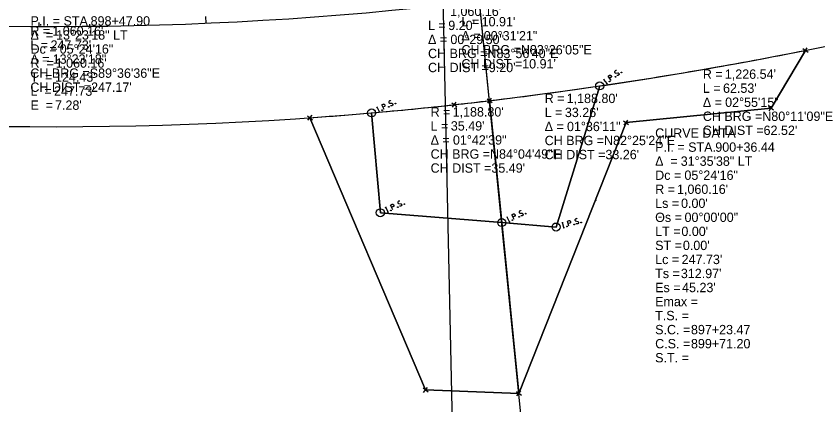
# Model space of a CAD drawing. Extents: x 2379325 to 2382869, y 256594 to 258871.
# Drawn here: x 2382072.5 to 2382312.6, y 257773.3 to 257889.6 of the extents above; entities that cross this region are included whole.
import ezdxf

# ---------------------------------------------------------------- set-up
doc = ezdxf.new("R2010")
doc.units = 0
for name, color, linetype in [('Default', 7, 'Continuous'), ('DR_P_Culvert3D', 7, 'Continuous'), ('DR_P_Dike', 7, 'Continuous'), ('DR_P_Ditch', 7, 'Continuous'), ('DR_P_Drainage_Area', 7, 'Continuous'), ('DR_P_Headwall', 7, 'Continuous'), ('DR_P_Storm_Sewer', 7, 'Continuous'), ('DR_X_Culvert', 7, 'Continuous'), ('DR_X_Culvert3D', 7, 'Continuous'), ('DR_X_Storm_Sewer', 7, 'Continuous'), ('PF_X_Ground_Line', 7, 'Continuous'), ('SC_Scratch1', 7, 'Continuous'), ('SC_Scratch2', 7, 'Continuous'), ('SC_Scratch4', 7, 'Continuous')]:
    doc.layers.add(name, color=color, linetype=linetype)

msp = doc.modelspace()

# ---------------------------------------------------------------- linework, layer by layer
at = {"layer": 'DR_P_Culvert3D'}
for p, q in [((2382298.56, 257862.08), (2382308.87, 257879.36)), ((2382255.15, 257857.75), (2382298.56, 257862.08)), ((2382160.54, 257859.2), (2382195.13, 257777.78)), ((2382223.08, 257776.74), (2382255.15, 257857.75)), ((2382195.13, 257777.78), (2382223.08, 257776.74))]:
    msp.add_line(p, q, dxfattribs=at)
at = {"layer": 'DR_P_Dike'}
for p, q in [((2382247.26, 257868.7), (2382234.2, 257826.5)), ((2382214.29, 257864.32), (2382217.95, 257827.82)), ((2382217.95, 257827.82), (2382214.29, 257864.32)), ((2382181.6, 257830.77), (2382178.99, 257860.65)), ((2382217.95, 257827.82), (2382181.6, 257830.77)), ((2382234.2, 257826.5), (2382217.95, 257827.82))]:
    msp.add_line(p, q, dxfattribs=at)
for centre, radius, start, end in [((2382069.07, 259082.23), 1226.54, 276.79975, 278.35358), ((2382084.05, 258946.67), 1090.16, 274.99624, 276.30412), ((2382069.07, 259082.23), 1226.54, 276.30412, 276.79975)]:
    msp.add_arc(centre, radius, start, end, dxfattribs=at)
at = {"layer": 'DR_P_Ditch'}
for points in [[(2382252.25, 257873.34), (2382252.21, 257873.34), (2382252.17, 257873.34), (2382252.07, 257873.31), (2382251.96, 257873.26), (2382251.89, 257873.21), (2382251.86, 257873.19), (2382251.77, 257873.07), (2382251.72, 257872.94), (2382251.72, 257872.81), (2382251.76, 257872.72), (2382251.81, 257872.66), (2382251.89, 257872.59), (2382252.01, 257872.57), (2382252.72, 257872.64), (2382252.8, 257872.63), (2382252.84, 257872.6), (2382252.91, 257872.55), (2382252.95, 257872.49), (2382252.99, 257872.43), (2382253.01, 257872.38), (2382253.03, 257872.32), (2382253.04, 257872.26), (2382253.05, 257872.22), (2382253.05, 257872.17), (2382253.03, 257872.13), (2382253.01, 257872.08), (2382253, 257872.05), (2382252.92, 257871.98), (2382252.8, 257871.89), (2382252.71, 257871.85), (2382252.54, 257871.83), (2382252.42, 257871.84)], [(2382253.67, 257872.81), (2382253.71, 257872.85), (2382253.75, 257872.85), (2382253.81, 257872.83), (2382253.85, 257872.78), (2382253.85, 257872.72), (2382253.84, 257872.68), (2382253.79, 257872.64), (2382253.75, 257872.64), (2382253.7, 257872.66), (2382253.66, 257872.71), (2382253.65, 257872.77), (2382253.67, 257872.81)], [(2382248.39, 257870.56), (2382248.67, 257870.77)], [(2382249.5, 257869.39), (2382248.53, 257870.67)], [(2382250.74, 257870.33), (2382249.78, 257871.61), (2382250.2, 257871.93), (2382250.25, 257871.95), (2382250.33, 257871.98), (2382250.37, 257871.98), (2382250.41, 257871.98), (2382250.49, 257871.95), (2382250.55, 257871.92), (2382250.63, 257871.86), (2382250.72, 257871.74), (2382250.74, 257871.69), (2382250.77, 257871.62), (2382250.79, 257871.52), (2382250.78, 257871.46), (2382250.76, 257871.42), (2382250.74, 257871.37), (2382250.67, 257871.31), (2382250.25, 257870.99)], [(2382250.13, 257870.14), (2382250.18, 257870.17), (2382250.22, 257870.17), (2382250.27, 257870.15), (2382250.31, 257870.1), (2382250.32, 257870.04), (2382250.31, 257870), (2382250.26, 257869.97), (2382250.22, 257869.97), (2382250.16, 257869.99), (2382250.12, 257870.04), (2382250.12, 257870.1), (2382250.13, 257870.14)], [(2382251.93, 257871.5), (2382251.97, 257871.53), (2382252.01, 257871.53), (2382252.07, 257871.51), (2382252.11, 257871.46), (2382252.11, 257871.4), (2382252.1, 257871.36), (2382252.05, 257871.32), (2382252.01, 257871.32), (2382251.96, 257871.35), (2382251.92, 257871.4), (2382251.91, 257871.46), (2382251.93, 257871.5)], [(2382249.36, 257869.28), (2382249.64, 257869.5)], [(2382182.71, 257861.61), (2382182, 257863.05), (2382182.47, 257863.28), (2382182.53, 257863.3), (2382182.61, 257863.31), (2382182.65, 257863.3), (2382182.69, 257863.29), (2382182.76, 257863.26), (2382182.81, 257863.21), (2382182.88, 257863.13), (2382182.95, 257863), (2382182.96, 257862.95), (2382182.97, 257862.87), (2382182.97, 257862.77), (2382182.95, 257862.72), (2382182.93, 257862.68), (2382182.89, 257862.63), (2382182.82, 257862.58), (2382182.35, 257862.35)], [(2382184.74, 257864.29), (2382184.71, 257864.3), (2382184.67, 257864.31), (2382184.57, 257864.3), (2382184.45, 257864.26), (2382184.37, 257864.23), (2382184.34, 257864.21), (2382184.23, 257864.11), (2382184.15, 257863.99), (2382184.13, 257863.87), (2382184.15, 257863.77), (2382184.19, 257863.7), (2382184.25, 257863.62), (2382184.37, 257863.58), (2382185.08, 257863.51), (2382185.15, 257863.49), (2382185.19, 257863.45), (2382185.25, 257863.4), (2382185.28, 257863.33), (2382185.31, 257863.26), (2382185.32, 257863.21), (2382185.33, 257863.14), (2382185.33, 257863.08), (2382185.33, 257863.04), (2382185.31, 257862.99), (2382185.29, 257862.96), (2382185.27, 257862.91), (2382185.24, 257862.89), (2382185.16, 257862.83), (2382185.02, 257862.76), (2382184.92, 257862.74), (2382184.75, 257862.76), (2382184.64, 257862.79)], [(2382186.04, 257863.51), (2382186.09, 257863.53), (2382186.13, 257863.53), (2382186.18, 257863.5), (2382186.21, 257863.44), (2382186.2, 257863.38), (2382186.19, 257863.34), (2382186.14, 257863.32), (2382186.1, 257863.33), (2382186.04, 257863.36), (2382186.02, 257863.41), (2382186.02, 257863.47), (2382186.04, 257863.51)], [(2382180.44, 257862.27), (2382180.76, 257862.43)], [(2382181.31, 257860.92), (2382180.6, 257862.35)], [(2382181.15, 257860.84), (2382181.47, 257861)], [(2382182.07, 257861.54), (2382182.12, 257861.56), (2382182.16, 257861.55), (2382182.22, 257861.52), (2382182.24, 257861.47), (2382182.24, 257861.41), (2382182.22, 257861.37), (2382182.17, 257861.34), (2382182.13, 257861.35), (2382182.08, 257861.38), (2382182.05, 257861.44), (2382182.05, 257861.5), (2382182.07, 257861.54)], [(2382184.09, 257862.54), (2382184.14, 257862.56), (2382184.18, 257862.55), (2382184.23, 257862.52), (2382184.26, 257862.47), (2382184.25, 257862.41), (2382184.23, 257862.37), (2382184.18, 257862.35), (2382184.14, 257862.35), (2382184.09, 257862.38), (2382184.06, 257862.44), (2382184.07, 257862.5), (2382184.09, 257862.54)], [(2382187.45, 257834.25), (2382187.42, 257834.26), (2382187.38, 257834.27), (2382187.27, 257834.26), (2382187.15, 257834.24), (2382187.07, 257834.2), (2382187.04, 257834.18), (2382186.93, 257834.09), (2382186.85, 257833.97), (2382186.82, 257833.85), (2382186.84, 257833.75), (2382186.88, 257833.68), (2382186.94, 257833.59), (2382187.06, 257833.55), (2382187.76, 257833.47), (2382187.84, 257833.44), (2382187.88, 257833.41), (2382187.93, 257833.35), (2382187.96, 257833.28), (2382187.98, 257833.21), (2382187.99, 257833.16), (2382188, 257833.09), (2382188, 257833.03), (2382188, 257832.99), (2382187.98, 257832.94), (2382187.96, 257832.91), (2382187.94, 257832.86), (2382187.91, 257832.84), (2382187.83, 257832.79), (2382187.69, 257832.72), (2382187.59, 257832.7), (2382187.42, 257832.72), (2382187.31, 257832.75)], [(2382183.09, 257832.35), (2382183.41, 257832.5)], [(2382183.93, 257830.97), (2382183.25, 257832.42)], [(2382185.35, 257831.63), (2382184.67, 257833.08), (2382185.15, 257833.31), (2382185.21, 257833.32), (2382185.29, 257833.33), (2382185.33, 257833.32), (2382185.37, 257833.31), (2382185.44, 257833.27), (2382185.49, 257833.23), (2382185.56, 257833.15), (2382185.62, 257833.01), (2382185.63, 257832.96), (2382185.64, 257832.88), (2382185.64, 257832.78), (2382185.62, 257832.73), (2382185.6, 257832.69), (2382185.56, 257832.65), (2382185.48, 257832.6), (2382185, 257832.37)], [(2382186.75, 257832.52), (2382186.8, 257832.54), (2382186.84, 257832.53), (2382186.89, 257832.5), (2382186.91, 257832.44), (2382186.91, 257832.38), (2382186.89, 257832.35), (2382186.84, 257832.32), (2382186.8, 257832.33), (2382186.74, 257832.37), (2382186.72, 257832.42), (2382186.73, 257832.48), (2382186.75, 257832.52)], [(2382188.73, 257833.44), (2382188.77, 257833.46), (2382188.82, 257833.45), (2382188.87, 257833.42), (2382188.89, 257833.37), (2382188.88, 257833.31), (2382188.87, 257833.27), (2382188.82, 257833.25), (2382188.77, 257833.25), (2382188.72, 257833.29), (2382188.7, 257833.34), (2382188.71, 257833.4), (2382188.73, 257833.44)], [(2382183.77, 257830.9), (2382184.09, 257831.05)], [(2382184.71, 257831.57), (2382184.76, 257831.59), (2382184.8, 257831.58), (2382184.85, 257831.55), (2382184.88, 257831.5), (2382184.87, 257831.44), (2382184.85, 257831.4), (2382184.8, 257831.38), (2382184.76, 257831.38), (2382184.71, 257831.42), (2382184.68, 257831.47), (2382184.69, 257831.53), (2382184.71, 257831.57)], [(2382219.43, 257829.42), (2382219.74, 257829.57)], [(2382220.28, 257828.05), (2382219.58, 257829.49)], [(2382221.69, 257828.73), (2382220.99, 257830.17), (2382221.47, 257830.4), (2382221.53, 257830.41), (2382221.61, 257830.42), (2382221.65, 257830.42), (2382221.69, 257830.41), (2382221.76, 257830.37), (2382221.81, 257830.33), (2382221.88, 257830.25), (2382221.94, 257830.11), (2382221.95, 257830.06), (2382221.97, 257829.98), (2382221.96, 257829.88), (2382221.94, 257829.83), (2382221.92, 257829.79), (2382221.88, 257829.75), (2382221.81, 257829.7), (2382221.33, 257829.47)], [(2382223.08, 257829.64), (2382223.12, 257829.66), (2382223.17, 257829.65), (2382223.22, 257829.62), (2382223.24, 257829.56), (2382223.24, 257829.5), (2382223.22, 257829.47), (2382223.17, 257829.44), (2382223.13, 257829.45), (2382223.08, 257829.48), (2382223.05, 257829.54), (2382223.06, 257829.6), (2382223.08, 257829.64)], [(2382223.75, 257831.38), (2382223.72, 257831.39), (2382223.68, 257831.4), (2382223.58, 257831.39), (2382223.46, 257831.36), (2382223.38, 257831.32), (2382223.35, 257831.31), (2382223.24, 257831.21), (2382223.16, 257831.09), (2382223.13, 257830.96), (2382223.16, 257830.86), (2382223.19, 257830.8), (2382223.25, 257830.71), (2382223.37, 257830.67), (2382224.08, 257830.6), (2382224.15, 257830.57), (2382224.19, 257830.54), (2382224.25, 257830.48), (2382224.28, 257830.41), (2382224.3, 257830.34), (2382224.31, 257830.29), (2382224.32, 257830.22), (2382224.32, 257830.17), (2382224.32, 257830.12), (2382224.31, 257830.08), (2382224.29, 257830.04), (2382224.26, 257830), (2382224.24, 257829.97), (2382224.15, 257829.92), (2382224.01, 257829.85), (2382223.91, 257829.83), (2382223.74, 257829.85), (2382223.63, 257829.88)], [(2382225.04, 257830.58), (2382225.09, 257830.61), (2382225.13, 257830.6), (2382225.18, 257830.57), (2382225.21, 257830.51), (2382225.2, 257830.45), (2382225.18, 257830.41), (2382225.13, 257830.39), (2382225.09, 257830.4), (2382225.04, 257830.43), (2382225.02, 257830.49), (2382225.02, 257830.55), (2382225.04, 257830.58)], [(2382220.12, 257827.97), (2382220.44, 257828.13)], [(2382221.05, 257828.66), (2382221.1, 257828.68), (2382221.14, 257828.68), (2382221.19, 257828.64), (2382221.22, 257828.59), (2382221.21, 257828.53), (2382221.19, 257828.49), (2382221.14, 257828.47), (2382221.1, 257828.48), (2382221.05, 257828.51), (2382221.02, 257828.56), (2382221.03, 257828.62), (2382221.05, 257828.66)], [(2382235.94, 257827.81), (2382236.28, 257827.9)], [(2382236.53, 257826.31), (2382236.11, 257827.86)], [(2382238.04, 257826.73), (2382237.62, 257828.27), (2382238.13, 257828.41), (2382238.18, 257828.41), (2382238.26, 257828.41), (2382238.3, 257828.4), (2382238.34, 257828.38), (2382238.4, 257828.33), (2382238.45, 257828.28), (2382238.5, 257828.19), (2382238.54, 257828.04), (2382238.54, 257827.99), (2382238.54, 257827.91), (2382238.52, 257827.82), (2382238.49, 257827.77), (2382238.46, 257827.73), (2382238.42, 257827.7), (2382238.33, 257827.66), (2382237.82, 257827.52)], [(2382239.57, 257827.37), (2382239.62, 257827.39), (2382239.66, 257827.37), (2382239.71, 257827.33), (2382239.72, 257827.27), (2382239.7, 257827.21), (2382239.68, 257827.18), (2382239.63, 257827.17), (2382239.59, 257827.18), (2382239.54, 257827.22), (2382239.52, 257827.28), (2382239.54, 257827.34), (2382239.57, 257827.37)], [(2382240.55, 257828.96), (2382240.52, 257828.98), (2382240.48, 257829), (2382240.38, 257829.01), (2382240.25, 257829), (2382240.17, 257828.98), (2382240.14, 257828.97), (2382240.01, 257828.89), (2382239.91, 257828.79), (2382239.86, 257828.67), (2382239.87, 257828.57), (2382239.89, 257828.49), (2382239.94, 257828.4), (2382240.04, 257828.34), (2382240.73, 257828.14), (2382240.8, 257828.1), (2382240.83, 257828.06), (2382240.87, 257827.99), (2382240.89, 257827.92), (2382240.9, 257827.84), (2382240.9, 257827.79), (2382240.9, 257827.73), (2382240.89, 257827.67), (2382240.88, 257827.63), (2382240.86, 257827.58), (2382240.83, 257827.55), (2382240.8, 257827.52), (2382240.77, 257827.49), (2382240.68, 257827.46), (2382240.53, 257827.42), (2382240.43, 257827.41), (2382240.26, 257827.46), (2382240.16, 257827.51)], [(2382241.67, 257827.95), (2382241.73, 257827.97), (2382241.76, 257827.95), (2382241.81, 257827.91), (2382241.83, 257827.85), (2382241.81, 257827.79), (2382241.78, 257827.76), (2382241.73, 257827.75), (2382241.69, 257827.76), (2382241.65, 257827.8), (2382241.63, 257827.86), (2382241.65, 257827.92), (2382241.67, 257827.95)], [(2382236.36, 257826.27), (2382236.7, 257826.36)], [(2382237.4, 257826.77), (2382237.45, 257826.79), (2382237.49, 257826.77), (2382237.54, 257826.73), (2382237.55, 257826.67), (2382237.54, 257826.62), (2382237.51, 257826.58), (2382237.46, 257826.57), (2382237.42, 257826.58), (2382237.37, 257826.62), (2382237.36, 257826.68), (2382237.38, 257826.74), (2382237.4, 257826.77)]]:
    msp.add_lwpolyline(points, dxfattribs=at)
for centre in [(2382247.26, 257868.7), (2382178.99, 257860.65), (2382181.6, 257830.77), (2382217.95, 257827.82), (2382234.2, 257826.5)]:
    msp.add_circle(centre, 1.2, dxfattribs=at)
at = {"layer": 'DR_P_Drainage_Area'}
for p, q in [((2382308.87, 257879.36), (2382298.56, 257862.08)), ((2382308.87, 257879.36), (2382298.56, 257862.08)), ((2382234.2, 257826.5), (2382247.26, 257868.7)), ((2382178.99, 257860.65), (2382181.6, 257830.77)), ((2382298.56, 257862.08), (2382255.15, 257857.75)), ((2382298.56, 257862.08), (2382255.15, 257857.75)), ((2382195.13, 257777.78), (2382160.54, 257859.2)), ((2382255.15, 257857.75), (2382223.08, 257776.74)), ((2382255.15, 257857.75), (2382223.08, 257776.74)), ((2382181.6, 257830.77), (2382217.95, 257827.82)), ((2382217.95, 257827.82), (2382223.08, 257776.74)), ((2382223.08, 257776.74), (2382217.95, 257827.82)), ((2382217.95, 257827.82), (2382234.2, 257826.5)), ((2382223.08, 257776.74), (2382217.95, 257827.82)), ((2382217.95, 257827.82), (2382234.2, 257826.5)), ((2382223.08, 257776.74), (2382195.13, 257777.78))]:
    msp.add_line(p, q, dxfattribs=at)
for centre, radius, start, end in [((2382069.07, 259082.23), 1226.54, 278.35358, 281.27454), ((2382069.07, 259082.23), 1226.54, 278.35358, 281.27454), ((2382084.05, 258946.67), 1090.16, 274.02344, 274.99624)]:
    msp.add_arc(centre, radius, start, end, dxfattribs=at)
at = {"layer": 'DR_P_Headwall'}
for centre, radius, start, end in [((2382069.07, 259082.23), 1226.54, 276.30412, 294.43398), ((2382084.05, 258946.67), 1090.16, 262.91573, 276.30412)]:
    msp.add_arc(centre, radius, start, end, dxfattribs=at)
at = {"layer": 'DR_P_Storm_Sewer'}
for p, q in [((2382308.08, 257879.87), (2382309.66, 257878.84)), ((2382308.36, 257878.57), (2382309.39, 257880.15)), ((2382203.01, 257863.69), (2382204.49, 257862.52)), ((2382203.17, 257862.36), (2382204.33, 257863.85)), ((2382213.54, 257864.88), (2382215.05, 257863.75)), ((2382213.73, 257863.56), (2382214.86, 257865.07)), ((2382297.78, 257862.61), (2382299.34, 257861.55)), ((2382298.03, 257861.3), (2382299.09, 257862.86)), ((2382159.82, 257859.81), (2382161.26, 257858.59)), ((2382159.93, 257858.48), (2382161.15, 257859.92)), ((2382254.39, 257858.3), (2382255.91, 257857.19)), ((2382254.6, 257856.98), (2382255.7, 257858.51)), ((2382194.39, 257778.36), (2382195.87, 257777.19)), ((2382194.54, 257777.04), (2382195.71, 257778.52)), ((2382222.33, 257777.31), (2382223.83, 257776.17)), ((2382222.5, 257775.99), (2382223.65, 257777.49))]:
    msp.add_line(p, q, dxfattribs=at)
at = {"layer": 'DR_X_Culvert3D'}
for p, q in [((2382129.48, 257887.49), (2382129.39, 257889.48)), ((2382079.49, 257886.52), (2382079.5, 257887.72))]:
    msp.add_line(p, q, dxfattribs=at)
at = {"layer": 'DR_X_Storm_Sewer'}
for q in [(2382211.21, 257895.08), (2382211.23, 257894.88)]:
    msp.add_line((2382240.29, 257605.16), q, dxfattribs=at)
at = {"layer": 'PF_X_Ground_Line'}
msp.add_line((2382227.19, 256666.69), (2382192.17, 258272.85), dxfattribs=at)
at = {"layer": 'SC_Scratch1'}
for centre in [(2382246.03, 257834.36), (2382220.35, 257805.56)]:
    msp.add_circle(centre, 0.05, dxfattribs=at)
at = {"layer": 'SC_Scratch2'}
msp.add_arc((2382084.05, 258946.67), 1060.16, 262.91573, 276.30412, dxfattribs=at)
at = {"layer": 'SC_Scratch4'}
for p, q in [((2382234.2, 257826.5), (2382247.26, 257868.7)), ((2382178.99, 257860.65), (2382181.6, 257830.77)), ((2382181.6, 257830.77), (2382217.95, 257827.82)), ((2382217.95, 257827.82), (2382234.2, 257826.5))]:
    msp.add_line(p, q, dxfattribs=at)

# ---------------------------------------------------------------- texts
at = {"layer": 'Default'}
for s, p in [("1,060.16'", (2382202.47, 257889.63)), ('L = ', (2382205.88, 257886.53)), ("10.91'", (2382211.92, 257886.53)), ('L = ', (2382195.88, 257885.43)), ("9.20'", (2382201.93, 257885.43)), ('R = ', (2382076.83, 257883.74)), ("1,060.16'", (2382083.41, 257883.74)), ('Δ = ', (2382205.88, 257882.33)), ('00°31\'21"', (2382212.56, 257882.33)), ('L = ', (2382076.83, 257879.54)), ("247.73'", (2382082.87, 257879.54)), ('Δ = ', (2382195.88, 257881.23)), ('00°29\'50"', (2382202.57, 257881.23)), ('CH BRG = ', (2382195.88, 257877.03)), ('CH BRG = ', (2382205.88, 257878.13)), ('N83°56\'40"E', (2382213.67, 257877.03)), ('N83°26\'05"E', (2382223.66, 257878.13)), ('Δ = ', (2382076.83, 257875.34)), ('13°23\'18"', (2382083.51, 257875.34)), ('CH DIST = ', (2382195.88, 257872.83)), ('CH DIST = ', (2382205.88, 257873.93)), ("9.20'", (2382214.07, 257872.83)), ("10.91'", (2382224.06, 257873.93)), ('CH BRG = ', (2382076.83, 257871.14)), ('S89°36\'36"E', (2382094.61, 257871.14)), ('R = ', (2382278.14, 257870.84)), ("1,226.54'", (2382284.72, 257870.84)), ('CH DIST = ', (2382076.83, 257866.94)), ("247.17'", (2382095.01, 257866.94)), ('L = ', (2382278.14, 257866.64)), ("62.53'", (2382284.18, 257866.64)), ('R = ', (2382230.79, 257863.59)), ("1,188.80'", (2382237.38, 257863.59)), ('Δ = ', (2382278.14, 257862.44)), ('02°55\'15"', (2382284.82, 257862.44)), ('R = ', (2382196.65, 257859.55)), ("1,188.80'", (2382203.24, 257859.55)), ('L = ', (2382230.79, 257859.39)), ("33.26'", (2382236.84, 257859.39)), ('CH BRG = ', (2382278.14, 257858.24)), ('N80°11\'09"E', (2382295.92, 257858.24)), ('L = ', (2382196.65, 257855.35)), ("35.49'", (2382202.7, 257855.35)), ('Δ = ', (2382230.79, 257855.19)), ('01°36\'11"', (2382237.47, 257855.19)), ('CH DIST = ', (2382278.14, 257854.04)), ("62.52'", (2382296.32, 257854.04)), ('Δ = ', (2382196.65, 257851.15)), ('01°42\'39"', (2382203.33, 257851.15)), ('CH BRG = ', (2382230.79, 257850.99)), ('N82°25\'24"E', (2382248.57, 257850.99)), ('CH BRG = ', (2382196.65, 257846.95)), ('N84°04\'49"E', (2382214.43, 257846.95)), ('CH DIST = ', (2382230.79, 257846.79)), ("33.26'", (2382248.98, 257846.79)), ('CH DIST = ', (2382196.65, 257842.75)), ("35.49'", (2382214.84, 257842.75))]:
    msp.add_text(s, height=2.8, dxfattribs=at).set_placement(p)
at = {"layer": 'DR_X_Culvert'}
for s, p in [('P.I. = STA. ', (2382076.88, 257886.76)), ('898+47.90', (2382094.87, 257886.76)), ('Δ  = ', (2382076.88, 257882.56)), ('13°23\'18" LT', (2382084.52, 257882.56)), ('Dc = ', (2382076.88, 257878.36)), ('05°24\'16"', (2382085.62, 257878.36)), ('R  = ', (2382076.88, 257874.16)), ("1,060.16'", (2382084.41, 257874.16)), ('T  = ', (2382076.88, 257869.96)), ("124.43'", (2382084.2, 257869.96)), ('L  = ', (2382076.88, 257865.76)), ("247.73'", (2382083.91, 257865.76)), ('E  = ', (2382076.88, 257861.56)), ("7.28'", (2382084.22, 257861.56)), ('CURVE DATA', (2382263.87, 257853.21)), ('P.I. = STA. ', (2382263.87, 257849.01)), ('900+36.44', (2382281.87, 257849.01)), ('Δ  = ', (2382263.87, 257844.81)), ('31°35\'38" LT', (2382271.52, 257844.81)), ('Dc = ', (2382263.87, 257840.61)), ('05°24\'16"', (2382272.62, 257840.61)), ('R = ', (2382263.87, 257836.41)), ("1,060.16'", (2382270.41, 257836.41)), ('Ls = ', (2382263.87, 257832.21)), ("0.00'", (2382271.62, 257832.21)), ('Θs = ', (2382263.87, 257828.01)), ('00°00\'00"', (2382272.66, 257828.01)), ('LT = ', (2382263.87, 257823.81)), ("0.00'", (2382271.72, 257823.81)), ('ST = ', (2382263.87, 257819.61)), ("0.00'", (2382272.17, 257819.61)), ('Lc = ', (2382263.87, 257815.41)), ("247.73'", (2382271.79, 257815.41)), ('Ts = ', (2382263.87, 257811.21)), ("312.97'", (2382271.56, 257811.21)), ('Es = ', (2382263.87, 257807.01)), ("45.23'", (2382271.93, 257807.01)), ('Emax = ', (2382263.87, 257802.81)), ('T.S. = ', (2382263.87, 257798.61)), ('S.C. = ', (2382263.87, 257794.41)), ('897+23.47', (2382274.58, 257794.41)), ('C.S. = ', (2382263.87, 257790.21)), ('899+71.20', (2382274.58, 257790.21)), ('S.T. = ', (2382263.87, 257786.01))]:
    msp.add_text(s, height=2.8, dxfattribs=at).set_placement(p)

doc.saveas('drawing.dxf')
